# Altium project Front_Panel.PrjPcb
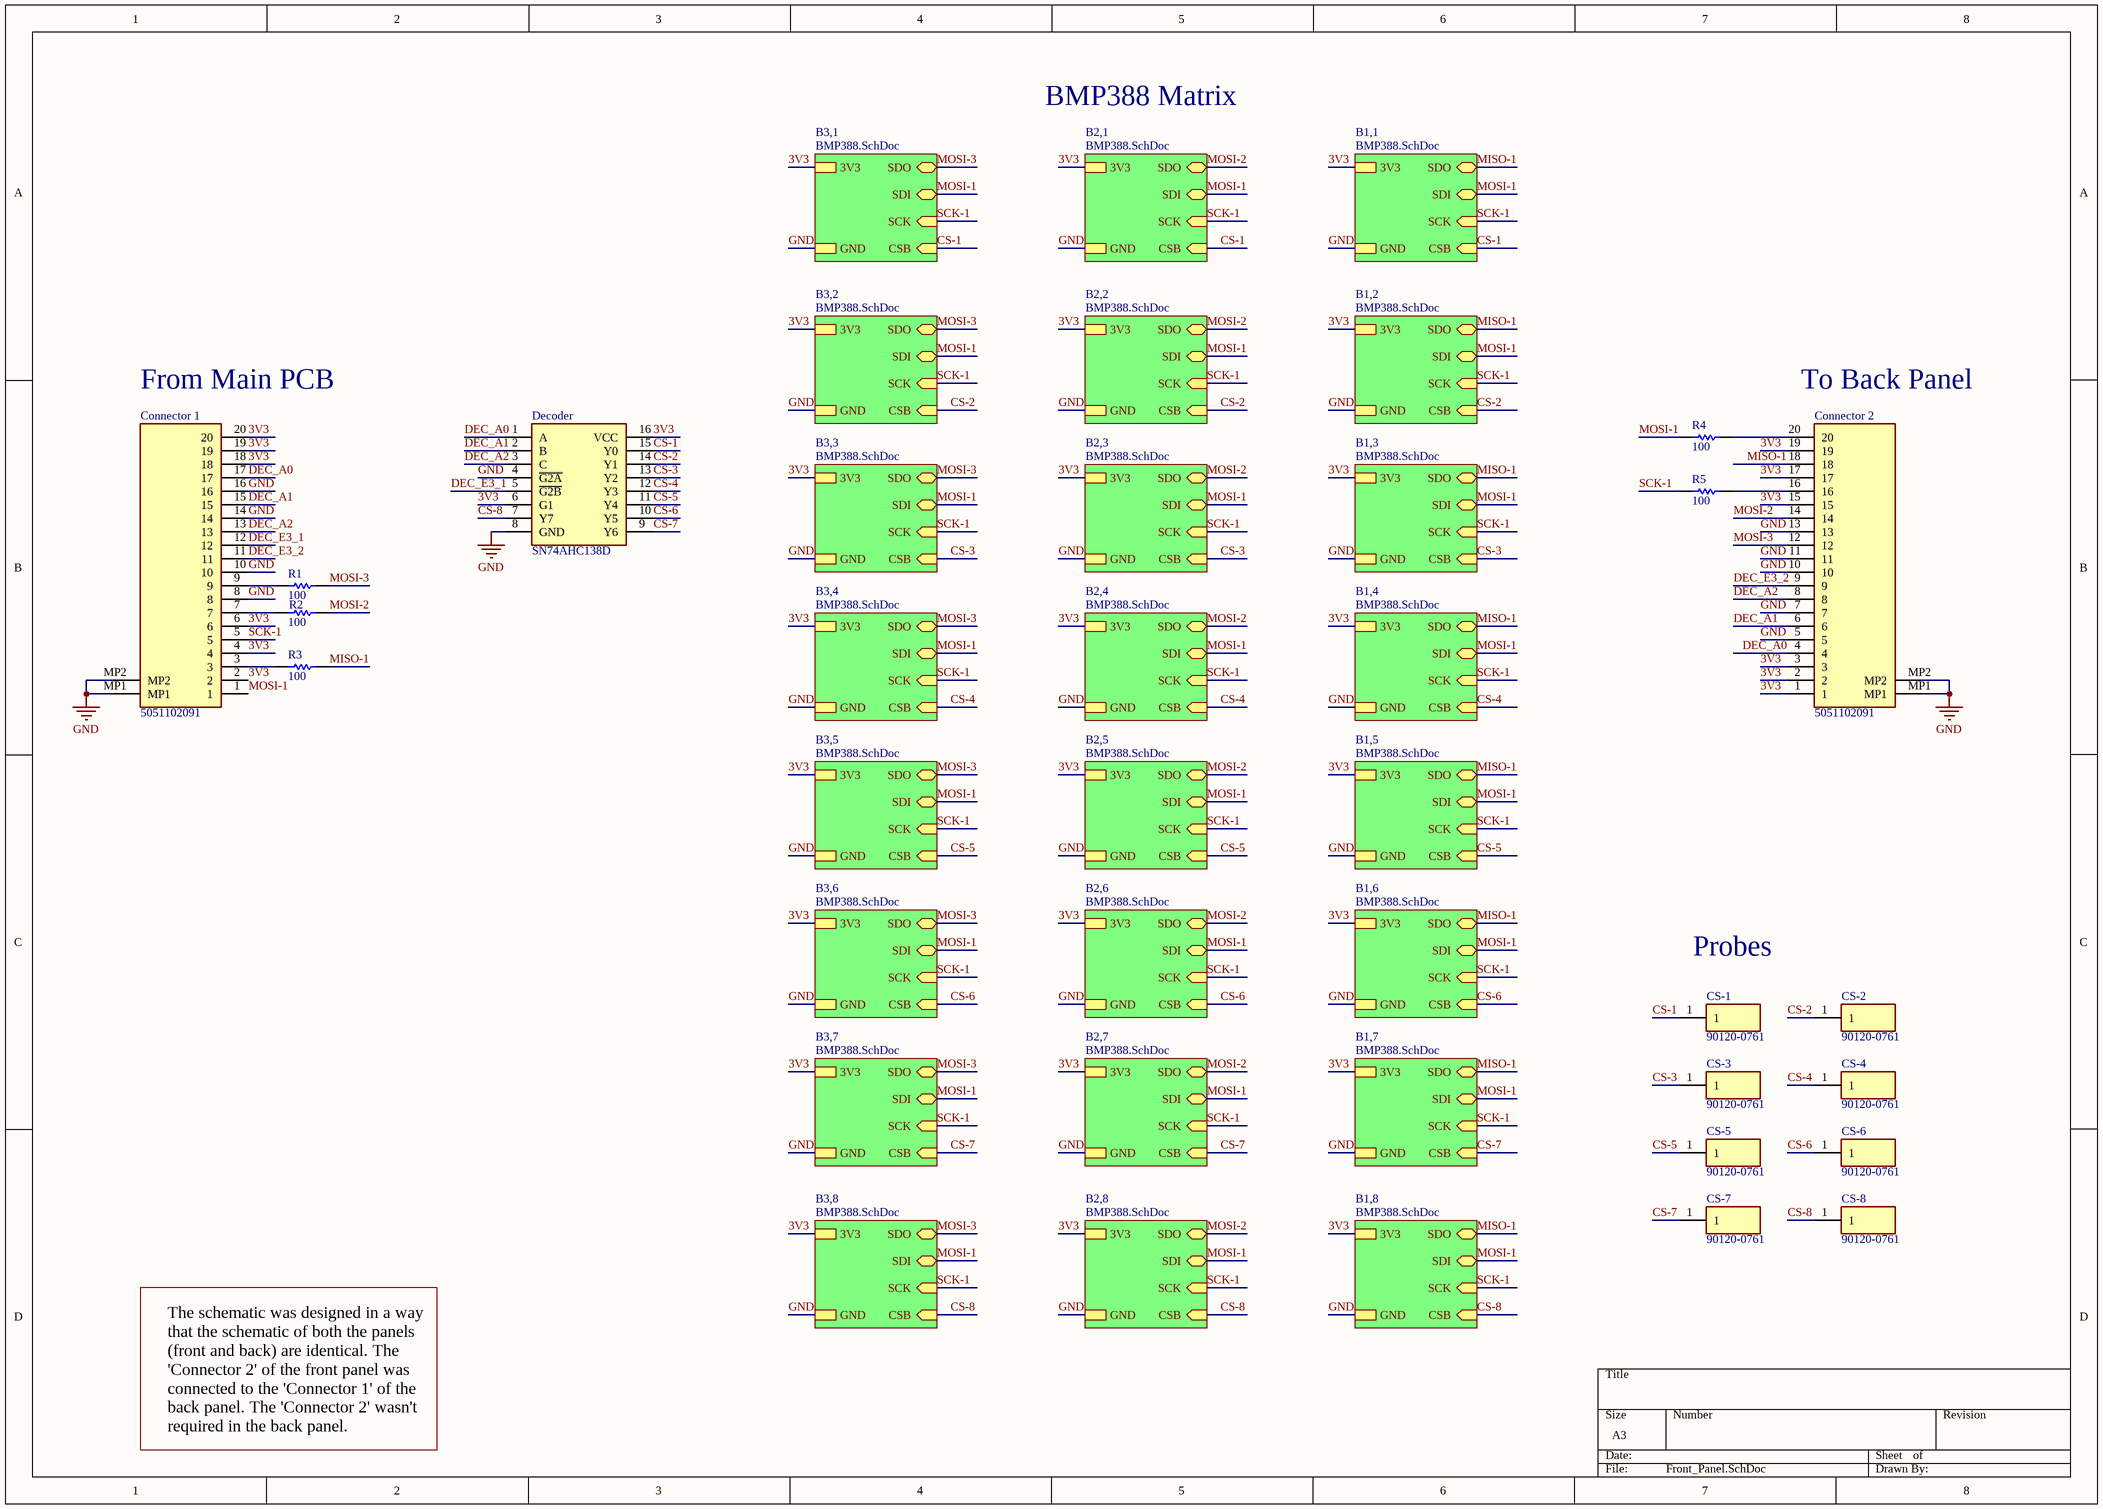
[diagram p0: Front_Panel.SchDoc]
2 sheets, 88 parts. Net scope: hierarchical (ports join the sheet entries above them; power ports are global).
Board file: BMP.PcbDoc
Sheets:
  Front_Panel.SchDoc
    B1,2 = BMP388.SchDoc
    B1,3 = BMP388.SchDoc
    B1,4 = BMP388.SchDoc
    B1,5 = BMP388.SchDoc
    B1,6 = BMP388.SchDoc
    B1,7 = BMP388.SchDoc
    B1,8 = BMP388.SchDoc
    B2,1 = BMP388.SchDoc
    B2,2 = BMP388.SchDoc
    B2,3 = BMP388.SchDoc
    B2,4 = BMP388.SchDoc
    B2,5 = BMP388.SchDoc
    B2,6 = BMP388.SchDoc
    B2,7 = BMP388.SchDoc
    B2,8 = BMP388.SchDoc
    B3,8 = BMP388.SchDoc
    B3,1 = BMP388.SchDoc
    B3,2 = BMP388.SchDoc
    B3,3 = BMP388.SchDoc
    B3,4 = BMP388.SchDoc
    B3,5 = BMP388.SchDoc
    B3,6 = BMP388.SchDoc
    B3,7 = BMP388.SchDoc
    B1,1 = BMP388.SchDoc

## Sheet Front_Panel.SchDoc
size A3

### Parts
Connector_1  5051102091  [5051102091]
Connector_2  5051102091  [5051102091]
CS-1  90120-0761  [HDRV1W90P0X254_1X1_232X249X560P]
CS-2  90120-0761  [HDRV1W90P0X254_1X1_232X249X560P]
CS-3  90120-0761  [HDRV1W90P0X254_1X1_232X249X560P]
CS-4  90120-0761  [HDRV1W90P0X254_1X1_232X249X560P]
CS-5  90120-0761  [HDRV1W90P0X254_1X1_232X249X560P]
CS-6  90120-0761  [HDRV1W90P0X254_1X1_232X249X560P]
CS-7  90120-0761  [HDRV1W90P0X254_1X1_232X249X560P]
CS-8  90120-0761  [HDRV1W90P0X254_1X1_232X249X560P]
Decoder  SN74AHC138D  [SOIC127P600X175-16N]
R1  value 100  [J1-0603]  (hidden comment: Res1)
R2  value 100  [J1-0603]  (hidden comment: Res1)
R3  value 100  [J1-0603]  (hidden comment: Res1)
R4  value 100  [J1-0603]  (hidden comment: Res1)
R5  value 100  [J1-0603]  (hidden comment: Res1)

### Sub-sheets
B1,1 = BMP388.SchDoc: SDO (bidir), SDI (bidir), SCK (in), CSB (in), 3V3, GND
B1,2 = BMP388.SchDoc: SDO (bidir), SDI (bidir), SCK (in), CSB (in), 3V3, GND
B1,3 = BMP388.SchDoc: SDO (bidir), SDI (bidir), SCK (in), CSB (in), 3V3, GND
B1,4 = BMP388.SchDoc: SDO (bidir), SDI (bidir), SCK (in), CSB (in), 3V3, GND
B1,5 = BMP388.SchDoc: SDO (bidir), SDI (bidir), SCK (in), CSB (in), 3V3, GND
B1,6 = BMP388.SchDoc: SDO (bidir), SDI (bidir), SCK (in), CSB (in), 3V3, GND
B1,7 = BMP388.SchDoc: SDO (bidir), SDI (bidir), SCK (in), CSB (in), 3V3, GND
B1,8 = BMP388.SchDoc: SDO (bidir), SDI (bidir), SCK (in), CSB (in), 3V3, GND
B2,1 = BMP388.SchDoc: SDO (bidir), SDI (bidir), SCK (in), CSB (in), 3V3, GND
B2,2 = BMP388.SchDoc: SDO (bidir), SDI (bidir), SCK (in), CSB (in), 3V3, GND
B2,3 = BMP388.SchDoc: SDO (bidir), SDI (bidir), SCK (in), CSB (in), 3V3, GND
B2,4 = BMP388.SchDoc: SDO (bidir), SDI (bidir), SCK (in), CSB (in), 3V3, GND
B2,5 = BMP388.SchDoc: SDO (bidir), SDI (bidir), SCK (in), CSB (in), 3V3, GND
B2,6 = BMP388.SchDoc: SDO (bidir), SDI (bidir), SCK (in), CSB (in), 3V3, GND
B2,7 = BMP388.SchDoc: SDO (bidir), SDI (bidir), SCK (in), CSB (in), 3V3, GND
B2,8 = BMP388.SchDoc: SDO (bidir), SDI (bidir), SCK (in), CSB (in), 3V3, GND
B3,1 = BMP388.SchDoc: SDO (bidir), SDI (bidir), SCK (in), CSB (in), 3V3, GND
B3,2 = BMP388.SchDoc: SDO (bidir), SDI (bidir), SCK (in), CSB (in), 3V3, GND
B3,3 = BMP388.SchDoc: SDO (bidir), SDI (bidir), SCK (in), CSB (in), 3V3, GND
B3,4 = BMP388.SchDoc: SDO (bidir), SDI (bidir), SCK (in), CSB (in), 3V3, GND
B3,5 = BMP388.SchDoc: SDO (bidir), SDI (bidir), SCK (in), CSB (in), 3V3, GND
B3,6 = BMP388.SchDoc: SDO (bidir), SDI (bidir), SCK (in), CSB (in), 3V3, GND
B3,7 = BMP388.SchDoc: SDO (bidir), SDI (bidir), SCK (in), CSB (in), 3V3, GND
B3,8 = BMP388.SchDoc: SDO (bidir), SDI (bidir), SCK (in), CSB (in), 3V3, GND

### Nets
GND: Connector_1.8 Connector_1.10 Connector_1.14 Connector_1.16 Connector_1.MP1 Connector_1.MP2 Connector_2.5 Connector_2.7 Connector_2.10 Connector_2.11 Connector_2.13 Connector_2.MP1 Connector_2.MP2 Decoder.4(~{G2A}) Decoder.8(GND) ; sheet B1,2/GND, sheet B1,3/GND, sheet B1,4/GND, sheet B1,5/GND, sheet B1,6/GND, sheet B1,7/GND, sheet B1,8/GND, sheet B2,1/GND, sheet B2,2/GND, sheet B2,3/GND, sheet B2,4/GND, sheet B2,5/GND, sheet B2,6/GND, sheet B2,7/GND, sheet B2,8/GND, sheet B3,8/GND, sheet B3,1/GND, sheet B3,2/GND, sheet B3,3/GND, sheet B3,4/GND, sheet B3,5/GND, sheet B3,6/GND, sheet B3,7/GND, sheet B1,1/GND
3V3: Connector_1.2 Connector_1.4 Connector_1.6 Connector_1.18 Connector_1.19 Connector_1.20 Connector_2.1 Connector_2.2 Connector_2.3 Connector_2.15 Connector_2.17 Connector_2.19 Decoder.6(G1) Decoder.16(VCC) ; sheet B1,2/3V3, sheet B1,3/3V3, sheet B1,4/3V3, sheet B1,5/3V3, sheet B1,6/3V3, sheet B1,7/3V3, sheet B1,8/3V3, sheet B2,1/3V3, sheet B2,2/3V3, sheet B2,3/3V3, sheet B2,4/3V3, sheet B2,5/3V3, sheet B2,6/3V3, sheet B2,7/3V3, sheet B2,8/3V3, sheet B3,8/3V3, sheet B3,1/3V3, sheet B3,2/3V3, sheet B3,3/3V3, sheet B3,4/3V3, sheet B3,5/3V3, sheet B3,6/3V3, sheet B3,7/3V3, sheet B1,1/3V3
CS-1: CS-1.1 Decoder.15(Y0) ; sheet B2,1/CSB, sheet B3,1/CSB, sheet B1,1/CSB
CS-2: CS-2.1 Decoder.14(Y1) ; sheet B1,2/CSB, sheet B2,2/CSB, sheet B3,2/CSB
CS-3: CS-3.1 Decoder.13(Y2) ; sheet B1,3/CSB, sheet B2,3/CSB, sheet B3,3/CSB
CS-4: CS-4.1 Decoder.12(Y3) ; sheet B1,4/CSB, sheet B2,4/CSB, sheet B3,4/CSB
CS-5: CS-5.1 Decoder.11(Y4) ; sheet B1,5/CSB, sheet B2,5/CSB, sheet B3,5/CSB
CS-6: CS-6.1 Decoder.10(Y5) ; sheet B1,6/CSB, sheet B2,6/CSB, sheet B3,6/CSB
CS-7: CS-7.1 Decoder.9(Y6) ; sheet B1,7/CSB, sheet B2,7/CSB, sheet B3,7/CSB
CS-8: CS-8.1 Decoder.7(Y7) ; sheet B1,8/CSB, sheet B2,8/CSB, sheet B3,8/CSB
DEC_A0: Connector_1.17 Connector_2.4 Decoder.1(A)
DEC_A1: Connector_1.15 Connector_2.6 Decoder.2(B)
DEC_A2: Connector_1.13 Connector_2.8 Decoder.3(C)
DEC_E3_1: Connector_1.12 Decoder.5(~{G2B})
DEC_E3_2: Connector_1.11 Connector_2.9
MISO-1: Connector_2.18 R3.1 ; sheet B1,2/SDO, sheet B1,3/SDO, sheet B1,4/SDO, sheet B1,5/SDO, sheet B1,6/SDO, sheet B1,7/SDO, sheet B1,8/SDO, sheet B1,1/SDO
MOSI-1: Connector_1.1 R4.1 ; sheet B1,2/SDI, sheet B1,3/SDI, sheet B1,4/SDI, sheet B1,5/SDI, sheet B1,6/SDI, sheet B1,7/SDI, sheet B1,8/SDI, sheet B2,1/SDI, sheet B2,2/SDI, sheet B2,3/SDI, sheet B2,4/SDI, sheet B2,5/SDI, sheet B2,6/SDI, sheet B2,7/SDI, sheet B2,8/SDI, sheet B3,8/SDI, sheet B3,1/SDI, sheet B3,2/SDI, sheet B3,3/SDI, sheet B3,4/SDI, sheet B3,5/SDI, sheet B3,6/SDI, sheet B3,7/SDI, sheet B1,1/SDI
MOSI-2: Connector_2.14 R2.1 ; sheet B2,1/SDO, sheet B2,2/SDO, sheet B2,3/SDO, sheet B2,4/SDO, sheet B2,5/SDO, sheet B2,6/SDO, sheet B2,7/SDO, sheet B2,8/SDO
MOSI-3: Connector_2.12 R1.1 ; sheet B3,8/SDO, sheet B3,1/SDO, sheet B3,2/SDO, sheet B3,3/SDO, sheet B3,4/SDO, sheet B3,5/SDO, sheet B3,6/SDO, sheet B3,7/SDO
SCK-1: Connector_1.5 R5.1 ; sheet B1,2/SCK, sheet B1,3/SCK, sheet B1,4/SCK, sheet B1,5/SCK, sheet B1,6/SCK, sheet B1,7/SCK, sheet B1,8/SCK, sheet B2,1/SCK, sheet B2,2/SCK, sheet B2,3/SCK, sheet B2,4/SCK, sheet B2,5/SCK, sheet B2,6/SCK, sheet B2,7/SCK, sheet B2,8/SCK, sheet B3,8/SCK, sheet B3,1/SCK, sheet B3,2/SCK, sheet B3,3/SCK, sheet B3,4/SCK, sheet B3,5/SCK, sheet B3,6/SCK, sheet B3,7/SCK, sheet B1,1/SCK
NetConnector_1_3: Connector_1.3 R3.2
NetConnector_1_7: Connector_1.7 R2.2
NetConnector_1_9: Connector_1.9 R1.2
NetConnector_2_16: Connector_2.16 R5.2
NetConnector_2_20: Connector_2.20 R4.2

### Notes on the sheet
- BMP388 Matrix
- (near Connector_1) From Main PCB
- (near Connector_2) To Back Panel
- Probes
- The schematic was designed in a way that the schematic of both the panels (front and back) are identical. The 'Connector 2' of the front panel was connected to the 'Connector 1' of the back panel. The 'Connector 2' wasn't required in the back panel.

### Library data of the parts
Connector_1 Connector_2 = 5051102091: Connector; Manufacturer_Name: Molex
CS-1-CS-8 = 90120-0761: Connector; Manufacturer_Name: Molex
Decoder = SN74AHC138D: Integrated Circuit; Manufacturer_Name: Texas Instruments
R1-R5 = Res1: Resistor

## Sheet BMP388.SchDoc
size A3
Used 24 times, as channels B1,2, B1,3, B1,4, B1,5, B1,6, B1,7, B1,8, B2,1, B2,2, B2,3, B2,4, B2,5, B2,6, B2,7, B2,8, B3,8, B3,1, B3,2, B3,3, B3,4, B3,5, B3,6, B3,7, B1,1. Parts and nets are listed once, with the designators drawn on the sheet.
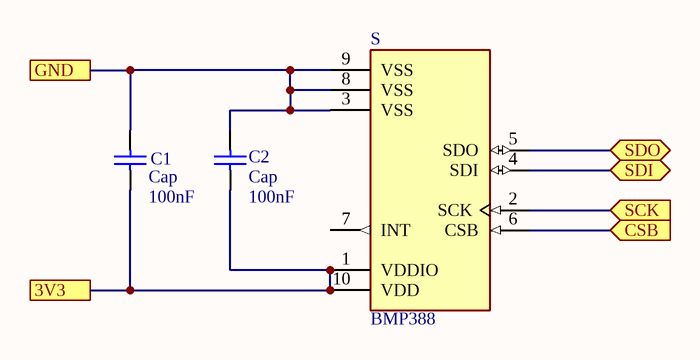
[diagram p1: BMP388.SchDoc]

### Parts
C1  Cap  value 100nF  [J1-0603]
C2  Cap  value 100nF  [J1-0603]
S  BMP388  [BMP388]

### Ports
3V3, CSB (in), GND, SCK (in), SDI (bidir), SDO (bidir)

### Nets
3V3: C1.2 C2.2 S.1(VDDIO) S.10(VDD) ; port 3V3
CSB: S.6(CSB) ; port CSB
GND: C1.1 C2.1 S.3(VSS) S.8(VSS) S.9(VSS) ; port GND
SCK: S.2(SCK) ; port SCK
SDI: S.4(SDI) ; port SDI
SDO: S.5(SDO) ; port SDO

Not connected (* = marked no-connect by the designer): S 7(INT)

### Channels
B1,2: designators end in _B1,2; ports 3V3=3V3 CSB=CS-2 GND=GND SCK=SCK-1 SDI=MOSI-1 SDO=MISO-1
B1,3: designators end in _B1,3; ports 3V3=3V3 CSB=CS-3 GND=GND SCK=SCK-1 SDI=MOSI-1 SDO=MISO-1
B1,4: designators end in _B1,4; ports 3V3=3V3 CSB=CS-4 GND=GND SCK=SCK-1 SDI=MOSI-1 SDO=MISO-1
B1,5: designators end in _B1,5; ports 3V3=3V3 CSB=CS-5 GND=GND SCK=SCK-1 SDI=MOSI-1 SDO=MISO-1
B1,6: designators end in _B1,6; ports 3V3=3V3 CSB=CS-6 GND=GND SCK=SCK-1 SDI=MOSI-1 SDO=MISO-1
B1,7: designators end in _B1,7; ports 3V3=3V3 CSB=CS-7 GND=GND SCK=SCK-1 SDI=MOSI-1 SDO=MISO-1
B1,8: designators end in _B1,8; ports 3V3=3V3 CSB=CS-8 GND=GND SCK=SCK-1 SDI=MOSI-1 SDO=MISO-1
B2,1: designators end in _B2,1; ports 3V3=3V3 CSB=CS-1 GND=GND SCK=SCK-1 SDI=MOSI-1 SDO=MOSI-2
B2,2: designators end in _B2,2; ports 3V3=3V3 CSB=CS-2 GND=GND SCK=SCK-1 SDI=MOSI-1 SDO=MOSI-2
B2,3: designators end in _B2,3; ports 3V3=3V3 CSB=CS-3 GND=GND SCK=SCK-1 SDI=MOSI-1 SDO=MOSI-2
B2,4: designators end in _B2,4; ports 3V3=3V3 CSB=CS-4 GND=GND SCK=SCK-1 SDI=MOSI-1 SDO=MOSI-2
B2,5: designators end in _B2,5; ports 3V3=3V3 CSB=CS-5 GND=GND SCK=SCK-1 SDI=MOSI-1 SDO=MOSI-2
B2,6: designators end in _B2,6; ports 3V3=3V3 CSB=CS-6 GND=GND SCK=SCK-1 SDI=MOSI-1 SDO=MOSI-2
B2,7: designators end in _B2,7; ports 3V3=3V3 CSB=CS-7 GND=GND SCK=SCK-1 SDI=MOSI-1 SDO=MOSI-2
B2,8: designators end in _B2,8; ports 3V3=3V3 CSB=CS-8 GND=GND SCK=SCK-1 SDI=MOSI-1 SDO=MOSI-2
B3,8: designators end in _B3,8; ports 3V3=3V3 CSB=CS-8 GND=GND SCK=SCK-1 SDI=MOSI-1 SDO=MOSI-3
B3,1: designators end in _B3,1; ports 3V3=3V3 CSB=CS-1 GND=GND SCK=SCK-1 SDI=MOSI-1 SDO=MOSI-3
B3,2: designators end in _B3,2; ports 3V3=3V3 CSB=CS-2 GND=GND SCK=SCK-1 SDI=MOSI-1 SDO=MOSI-3
B3,3: designators end in _B3,3; ports 3V3=3V3 CSB=CS-3 GND=GND SCK=SCK-1 SDI=MOSI-1 SDO=MOSI-3
B3,4: designators end in _B3,4; ports 3V3=3V3 CSB=CS-4 GND=GND SCK=SCK-1 SDI=MOSI-1 SDO=MOSI-3
B3,5: designators end in _B3,5; ports 3V3=3V3 CSB=CS-5 GND=GND SCK=SCK-1 SDI=MOSI-1 SDO=MOSI-3
B3,6: designators end in _B3,6; ports 3V3=3V3 CSB=CS-6 GND=GND SCK=SCK-1 SDI=MOSI-1 SDO=MOSI-3
B3,7: designators end in _B3,7; ports 3V3=3V3 CSB=CS-7 GND=GND SCK=SCK-1 SDI=MOSI-1 SDO=MOSI-3
B1,1: designators end in _B1,1; ports 3V3=3V3 CSB=CS-1 GND=GND SCK=SCK-1 SDI=MOSI-1 SDO=MISO-1

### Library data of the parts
C1 C2 = Cap: Capacitor
S = BMP388: Pressure Sensor 4.35PSI ~ 18.13PSI _30kPa ~ 125kPa_ Absolute 10-WFLGA; MF: Bosch Sensortec

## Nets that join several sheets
GND: Front_Panel (15 pins), B1,2 (5 pins), B1,3 (5 pins), B1,4 (5 pins), B1,5 (5 pins), B1,6 (5 pins), B1,7 (5 pins), B1,8 (5 pins), B2,1 (5 pins), B2,2 (5 pins), B2,3 (5 pins), B2,4 (5 pins), B2,5 (5 pins), B2,6 (5 pins), B2,7 (5 pins), B2,8 (5 pins), B3,8 (5 pins), B3,1 (5 pins), B3,2 (5 pins), B3,3 (5 pins), B3,4 (5 pins), B3,5 (5 pins), B3,6 (5 pins), B3,7 (5 pins), B1,1 (5 pins)
3V3: Front_Panel (14 pins), B1,2 (C1_B1,2.2 C2_B1,2.2 S_B1,2.1 S_B1,2.10), B1,3 (C1_B1,3.2 C2_B1,3.2 S_B1,3.1 S_B1,3.10), B1,4 (C1_B1,4.2 C2_B1,4.2 S_B1,4.1 S_B1,4.10), B1,5 (C1_B1,5.2 C2_B1,5.2 S_B1,5.1 S_B1,5.10), B1,6 (C1_B1,6.2 C2_B1,6.2 S_B1,6.1 S_B1,6.10), B1,7 (C1_B1,7.2 C2_B1,7.2 S_B1,7.1 S_B1,7.10), B1,8 (C1_B1,8.2 C2_B1,8.2 S_B1,8.1 S_B1,8.10), B2,1 (C1_B2,1.2 C2_B2,1.2 S_B2,1.1 S_B2,1.10), B2,2 (C1_B2,2.2 C2_B2,2.2 S_B2,2.1 S_B2,2.10), B2,3 (C1_B2,3.2 C2_B2,3.2 S_B2,3.1 S_B2,3.10), B2,4 (C1_B2,4.2 C2_B2,4.2 S_B2,4.1 S_B2,4.10), B2,5 (C1_B2,5.2 C2_B2,5.2 S_B2,5.1 S_B2,5.10), B2,6 (C1_B2,6.2 C2_B2,6.2 S_B2,6.1 S_B2,6.10), B2,7 (C1_B2,7.2 C2_B2,7.2 S_B2,7.1 S_B2,7.10), B2,8 (C1_B2,8.2 C2_B2,8.2 S_B2,8.1 S_B2,8.10), B3,8 (C1_B3,8.2 C2_B3,8.2 S_B3,8.1 S_B3,8.10), B3,1 (C1_B3,1.2 C2_B3,1.2 S_B3,1.1 S_B3,1.10), B3,2 (C1_B3,2.2 C2_B3,2.2 S_B3,2.1 S_B3,2.10), B3,3 (C1_B3,3.2 C2_B3,3.2 S_B3,3.1 S_B3,3.10), B3,4 (C1_B3,4.2 C2_B3,4.2 S_B3,4.1 S_B3,4.10), B3,5 (C1_B3,5.2 C2_B3,5.2 S_B3,5.1 S_B3,5.10), B3,6 (C1_B3,6.2 C2_B3,6.2 S_B3,6.1 S_B3,6.10), B3,7 (C1_B3,7.2 C2_B3,7.2 S_B3,7.1 S_B3,7.10), B1,1 (C1_B1,1.2 C2_B1,1.2 S_B1,1.1 S_B1,1.10)
CS-1: Front_Panel (CS-1.1 Decoder.15), B2,1 (S_B2,1.6), B3,1 (S_B3,1.6), B1,1 (S_B1,1.6)
CS-2: Front_Panel (CS-2.1 Decoder.14), B1,2 (S_B1,2.6), B2,2 (S_B2,2.6), B3,2 (S_B3,2.6)
CS-3: Front_Panel (CS-3.1 Decoder.13), B1,3 (S_B1,3.6), B2,3 (S_B2,3.6), B3,3 (S_B3,3.6)
CS-4: Front_Panel (CS-4.1 Decoder.12), B1,4 (S_B1,4.6), B2,4 (S_B2,4.6), B3,4 (S_B3,4.6)
CS-5: Front_Panel (CS-5.1 Decoder.11), B1,5 (S_B1,5.6), B2,5 (S_B2,5.6), B3,5 (S_B3,5.6)
CS-6: Front_Panel (CS-6.1 Decoder.10), B1,6 (S_B1,6.6), B2,6 (S_B2,6.6), B3,6 (S_B3,6.6)
CS-7: Front_Panel (CS-7.1 Decoder.9), B1,7 (S_B1,7.6), B2,7 (S_B2,7.6), B3,7 (S_B3,7.6)
CS-8: Front_Panel (CS-8.1 Decoder.7), B1,8 (S_B1,8.6), B2,8 (S_B2,8.6), B3,8 (S_B3,8.6)
MISO-1: Front_Panel (Connector_2.18 R3.1), B1,2 (S_B1,2.5), B1,3 (S_B1,3.5), B1,4 (S_B1,4.5), B1,5 (S_B1,5.5), B1,6 (S_B1,6.5), B1,7 (S_B1,7.5), B1,8 (S_B1,8.5), B1,1 (S_B1,1.5)
MOSI-1: Front_Panel (Connector_1.1 R4.1), B1,2 (S_B1,2.4), B1,3 (S_B1,3.4), B1,4 (S_B1,4.4), B1,5 (S_B1,5.4), B1,6 (S_B1,6.4), B1,7 (S_B1,7.4), B1,8 (S_B1,8.4), B2,1 (S_B2,1.4), B2,2 (S_B2,2.4), B2,3 (S_B2,3.4), B2,4 (S_B2,4.4), B2,5 (S_B2,5.4), B2,6 (S_B2,6.4), B2,7 (S_B2,7.4), B2,8 (S_B2,8.4), B3,8 (S_B3,8.4), B3,1 (S_B3,1.4), B3,2 (S_B3,2.4), B3,3 (S_B3,3.4), B3,4 (S_B3,4.4), B3,5 (S_B3,5.4), B3,6 (S_B3,6.4), B3,7 (S_B3,7.4), B1,1 (S_B1,1.4)
MOSI-2: Front_Panel (Connector_2.14 R2.1), B2,1 (S_B2,1.5), B2,2 (S_B2,2.5), B2,3 (S_B2,3.5), B2,4 (S_B2,4.5), B2,5 (S_B2,5.5), B2,6 (S_B2,6.5), B2,7 (S_B2,7.5), B2,8 (S_B2,8.5)
MOSI-3: Front_Panel (Connector_2.12 R1.1), B3,8 (S_B3,8.5), B3,1 (S_B3,1.5), B3,2 (S_B3,2.5), B3,3 (S_B3,3.5), B3,4 (S_B3,4.5), B3,5 (S_B3,5.5), B3,6 (S_B3,6.5), B3,7 (S_B3,7.5)
SCK-1: Front_Panel (Connector_1.5 R5.1), B1,2 (S_B1,2.2), B1,3 (S_B1,3.2), B1,4 (S_B1,4.2), B1,5 (S_B1,5.2), B1,6 (S_B1,6.2), B1,7 (S_B1,7.2), B1,8 (S_B1,8.2), B2,1 (S_B2,1.2), B2,2 (S_B2,2.2), B2,3 (S_B2,3.2), B2,4 (S_B2,4.2), B2,5 (S_B2,5.2), B2,6 (S_B2,6.2), B2,7 (S_B2,7.2), B2,8 (S_B2,8.2), B3,8 (S_B3,8.2), B3,1 (S_B3,1.2), B3,2 (S_B3,2.2), B3,3 (S_B3,3.2), B3,4 (S_B3,4.2), B3,5 (S_B3,5.2), B3,6 (S_B3,6.2), B3,7 (S_B3,7.2), B1,1 (S_B1,1.2)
